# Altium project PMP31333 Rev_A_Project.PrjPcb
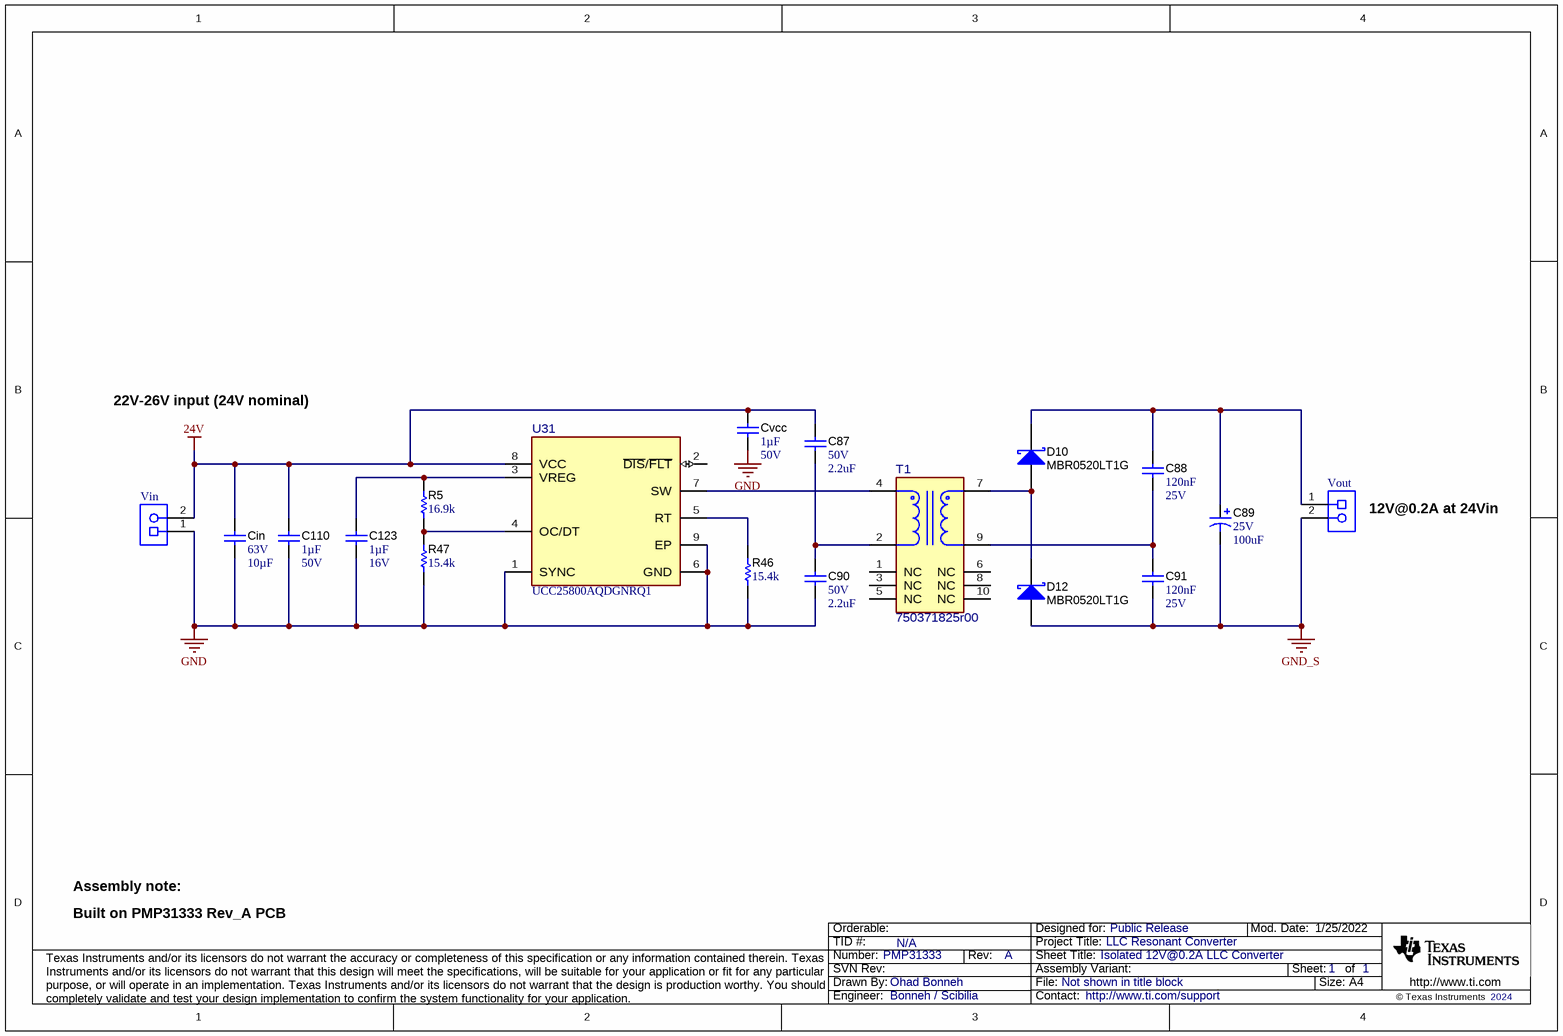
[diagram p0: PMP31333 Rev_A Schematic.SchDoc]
CopyrightYear: 2024; PCB_Layout: Ohad Bonneh; PCB_Rev: A; PRJ_Customer: Public Release; PRJ_Engineer: Bonneh / Scibilia; PRJ_Number: PMP31333; PRJ_Title: LLC Resonant Converter; SCH_Rev: A; TechSupport: http://www.ti.com/support; TID: N/A
1 sheet, 18 parts. Net scope: global (net labels, ports and power ports of the same name join across sheets).
Board file: PMP31333 Rev_A PCB.PcbDoc

## Sheet PMP31333 Rev_A Schematic.SchDoc: Isolated 12V@0.2A LLC Converter
size A4; Date: Not shown in title block; ApprovedBy: Not shown in title block; CheckedBy: Not shown in title block; Author: Not shown in title block; CompanyName: Not shown in title block; DrawnBy: Ohad Bonneh; Engineer: Not shown in title block; Organization: Not shown in title block; Address1: Not shown in title block; Address2: Not shown in title block; Address3: Not shown in title block; Address4: Not shown in title block; DocumentNumber: 1; Revision: Use project parameter SCH_Rev; SheetNumber: 1; SheetTotal: 1; PageSetup: Record=PageOptions¦CenterHorizontal=True¦CenterVertical=True¦PrintScale=1.00¦XCorrection=1.00¦YCorrection=1.00¦PrintKind=0¦BorderSize=5000000¦LeftOffset=0¦BottomOffset=0¦Orientation=2¦PaperLength=1000¦PaperWidth=1000¦Scale=100¦PaperSource=15¦PrintQuality=600¦MediaType=1¦DitherType=10¦PaperKind=Letter¦PrintScaleMode=1

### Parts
C87  VDC_V: 50V  ValueDisplayed: 2.2uF  [0603]  (hidden comment: GRM188R61H225KE11D)
C88  Cap_F: 120nF  VDC_V: 25V  [0603]  (hidden comment: GRM188R71E124KA01D)
C89  VDC_V: 25V  ValueDisplayed: 100uF  [WCAP-ASLI_630x770]  (hidden comment: 865080445010)
C90  VDC_V: 50V  ValueDisplayed: 2.2uF  [0603]  (hidden comment: GRM188R61H225KE11D)
C91  Cap_F: 120nF  VDC_V: 25V  [0603]  (hidden comment: GRM188R71E124KA01D)
C110  Cap_F: 1µF  VDC_V: 50V  [0805_HV]  (hidden comment: CGA4J3X7R1H105K125AB)
C123  Cap_F: 1µF  VDC_V: 16V  [0603]  (hidden comment: GCM188R71C105KA64J)
Cin  VDC_V: 63V  ValueDisplayed: 10µF  [1210_270]  (hidden comment: GRM32ER71J106MA12L)
Cvcc  Cap_F: 1µF  VDC_V: 50V  [0805_HV]  (hidden comment: CGA4J3X7R1H105K125AB)
D10  MBR0520LT1G  [SOD-123]
D12  MBR0520LT1G  [SOD-123]
R5  ValueDisplayed: 16.9k  [0603]  (hidden comment: CRCW060316K9FKEA)
R46  ValueDisplayed: 15.4k  [0603]  (hidden comment: CRCW060315K4FKEA)
R47  ValueDisplayed: 15.4k  [0603]  (hidden comment: CRCW060315K4FKEA)
T1  750371825r00  [FP-750371825r00_SMT_XFRMR_16MM31_13MM97-MFG]
U31  UCC25800AQDGNRQ1  [DGN0008G-MFG]
Vin  691214110002S  [FP-691214110002S_HDR2-MFG]  (value not drawn)
Vout  691214110002S  [FP-691214110002S_HDR2-MFG]  (value not drawn)

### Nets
24V: C87.1 C110.1 Cin.1 Cvcc.1 U31.8(VCC) Vin.2
GND: C90.2 C110.2 C123.2 Cin.2 Cvcc.2 R46.1 R47.1 U31.1(SYNC) U31.6(GND) U31.9(EP) Vin.1
GND_S: C89.2(-) C91.2 D12.2(A) Vout.2
NetC87_2: C87.2 C90.1 T1.2
NetC88_1: C88.1 C89.1(+) D10.1(K) Vout.1
NetC88_2: C88.2 C91.1 T1.9
NetC123_1: C123.1 R5.2 U31.3(VREG)
NetD10_2: D10.2(A) D12.1(K) T1.7
NetR5_1: R5.1 R47.2 U31.4(OC/DT)
NetR46_2: R46.2 U31.5(RT)
NetT1_4: T1.4 U31.7(SW)

Not connected (* = marked no-connect by the designer): T1 1(NC) 3(NC) 5(NC) 6(NC) 8(NC) 10(NC); U31 2(~{DIS}/~{FLT})

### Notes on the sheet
- 22V-26V input (24V nominal)
- (near Vout) 12V@0.2A at 24Vin
- Assembly note:
- Built on PMP31333 Rev_A PCB

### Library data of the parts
C87 C90 = CMP-0007353-5: CAP, CERM, 2.2 uF, 50 V, +/- 10%, X5R, 0603; Manufacturer: MuRata; TaMin_C: -55°C; Polarized: N; SizeAreaWB_mm2: 4.68; Value1: Unknown; U/M: EA; Value: 2.2uF; TaMax_C: 85°C; SizeZ_mm: 1; SizeX_mm: 1.6; SizeY_mm: 0.8; SizeArea_mm2: 1.28; Cap_F: 2.2µF; AEC Category: Q200
C88 C91 = CMP-0007408-4: CAP, CERM, 0.12 uF, 25 V, +/- 10%, X7R, 0603; Manufacturer: MuRata; TaMin_C: -55°C; Polarized: N; SizeAreaWB_mm2: 4.68; Value1: Unknown; U/M: EA; Value: 0.12uF; TaMax_C: 125°C; SizeZ_mm: 1; SizeX_mm: 1.6; SizeY_mm: 0.8; SizeArea_mm2: 1.28; AEC Category: Q200
C89 = CMP-0010559-1: CAP, AL, 100 uF, 25 V, +/- 20%, SMD; Manufacturer: Wurth Elektronik; TaMin_C: -55°C; Polarized: Y; SizeAreaWB_mm2: 79.98; Value1: Unknown; U/M: EA; Value: 100uF; TaMax_C: 105°C; SizeZ_mm: 7.7; SizeX_mm: 7.3; SizeY_mm: 6.6; Cap_Case: 6.3x7.7mm; SizeArea_mm2: 48.18; CompType: Capacitor; AEC Qualified: N; Cap_F: 100µF; IRMS_A: 290mA; AEC Category: Q200
C110 Cvcc = CMP-0007976-2: CAP, CERM, 1 uF, 50 V, +/- 10%, X7R, AEC-Q200 Grade 1, 0805; Manufacturer: TDK; TaMin_C: -55°C; ESR_ohm: 8.782m; Polarized: N; SizeAreaWB_mm2: 6.75; Value1: 0.008782 ohm; U/M: EA; Value: 1uF; TaMax_C: 125°C; SizeZ_mm: 1.45; SizeX_mm: 2; SizeY_mm: 1.25; Cap_Case: 0805; SizeArea_mm2: 2.5; AEC Qualified: Y; IRMS_A: 2.2049A; AEC Grade: 1; AEC Category: Q200
C123 = CMP-0079154-1: CAP, CERM, 1 µF, 16 V,+/- 10%, X7R, AEC-Q200 Grade 1, 0603; Manufacturer: MuRata; SizeAreaWB_mm2: 4.68; SizeArea_mm2: 1.28; AEC Qualified: Y; AEC Category: Q200; Value: 1uF; TaMax_C: 125°C; SizeZ_mm: 1; Polarized: N; TaMin_C: -55°C; SizeY_mm: 0.8; U/M: EA; SizeX_mm: 1.6
Cin = CMP-0079609-1: CAP, CERM, 10 µF, 63 V,+/- 20%, X7R, 1210; Manufacturer: MuRata; TaMin_C: -55°C; Polarized: N; SizeAreaWB_mm2: 14.7; U/M: EA; Value: 10uF; TaMax_C: 125°C; SizeZ_mm: 2.7; SizeX_mm: 3.2; SizeY_mm: 2.5; Cap_Case: 1210; SizeArea_mm2: 8; AEC Category: Q200
D10 D12 = CMP-0028524-2: Diode, Schottky, 20 V, 0.5 A, SOD-123; Manufacturer: ON Semiconductor; Green_REACh: Passed; TJmax_C: 125°C; Value1: 0.5A; SizeZ_mm: 1.35; Value2: 0.385V; Vf_V: 385mV; AEC Category: Q101; SizeY_mm: 1.7; Value: 20V; Io_A: 500mA; SizeX_mm: 3.85; Green_Lifecycle: Active; RJC_CperW: 150; SizeAreaWB_mm2: 13.095; SizeArea_mm2: 6.545
R5 = CMP-0022081-4: RES, 16.9 k, 1%, 0.1 W, AEC-Q200 Grade 0, 0603; Manufacturer: Vishay-Dale; Power_W: 100mW; TempCo: 100 ppm/C; Value_Code: 16k9; Value: 16.9k; EIA_Code: E96; SizeX_mm: 1.6; SizeY_mm: 0.8; SizeZ_mm: 1; Value2: 0.1W; SizeArea_mm2: 1.28; AEC Qualified: Y; VDC_V: 75V; AEC Category: Q200; AEC Grade: 0
R46 R47 = CMP-0022067-4: RES, 15.4 k, 1%, 0.1 W, AEC-Q200 Grade 0, 0603; Manufacturer: Vishay-Dale; Power_W: 100mW; TempCo: 100 ppm/C; Value_Code: 15k4; Value: 15.4k; EIA_Code: E96; SizeX_mm: 1.6; SizeY_mm: 0.8; SizeZ_mm: 1; Value2: 0.1W; SizeArea_mm2: 1.28; AEC Qualified: Y; VDC_V: 75V; AEC Category: Q200; AEC Grade: 0
T1 = CMP-0121486-1: TRANSFORMER; Manufacturer: Wurth Electronics; DCR_ohm: 0.15; Ind_H: 18.1µH; Ns1toNp: 1.78:1; Rsec1_ohm: 50m; SizeZ_mm: 12.7mm; AEC Qualified: No; Frequency_Fixed: 500kHz; Voltage_Isolation_Vrms: 3kV
U31 = CMP-0088494-2: Open Loop LLC Transformer Driver for Isolated Bias Supplies; Manufacturer: Texas Instruments; Min Supply Voltage: 12V; SizeZ_mm: 1.1mm; Number Of Outputs: 1; Standoff Height: 0.05mm; AEC Category: Q200; Max Duty Cycle: 50%; TaMin_C: -40°C; TJmax_C: +150°C; AEC Qualified: No; Switching Frequency: 100-2000kHz; CompType: IC; Max Supply Voltage: 36V; TaMax_C: +125°C; Output Type: Other; Nominal Supply Current: 500uA
Vin Vout = CMP-0093089-2: 2 Position Wire to Board Terminal Block Horizontal with Board 0.138" (3.50mm) Through Hole; Manufacturer: Wurth; ContactFinish: Tin,Nickel; AEC Qualified: No; Max Wire Gauge: 16; Voltage_V: 300V; SizeZ_mm: 9.2mm; Current_A: 10A; DUT-Pitch_mm: 3.5mm; Min Wire Gauge: 30; Conn Gender: Female; Row_Count: 1; Is Female: yes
